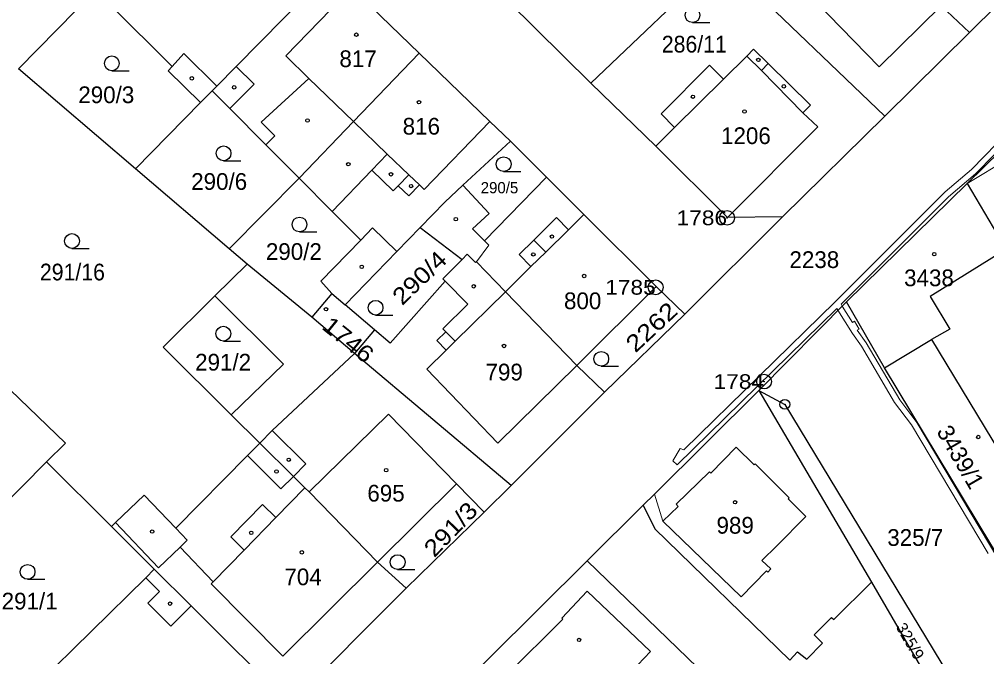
# Model space of a CAD drawing. Extents: x -679733 to -673243, y -1075091 to -1066557.
# Drawn here: x -676172.4 to -676074.1, y -1072237.3 to -1072172.5 of the extents above; entities that cross this region are included whole.
import ezdxf
from ezdxf.enums import TextEntityAlignment as Align

# ---------------------------------------------------------------- set-up
doc = ezdxf.new("R2010")
doc.units = 0
doc.header["$LTSCALE"] = 0.68
for name, color, linetype, lineweight in [('1', 7, 'Continuous', 25), ('13', 7, 'Continuous', 13), ('3', 7, 'Continuous', 25), ('4', 7, 'Continuous', 13), ('5', 7, 'Continuous', 25), ('8', 7, 'Continuous', 25)]:
    doc.layers.add(name, color=color, linetype=linetype, lineweight=lineweight)
doc.layers.add('2', color=7, linetype='Continuous')

msp = doc.modelspace()

# ---------------------------------------------------------------- linework, layer by layer
at = {"layer": '1'}
for p, q in [((-676075.84, -1072173.87), (-676078.75, -1072171.15)), ((-676160.6, -1072187.71), (-676153.99, -1072180.99)), ((-676127.33, -1072189.39), (-676122.5, -1072184.89)), ((-676143.98, -1072188.65), (-676151.09, -1072195.83)), ((-676088.36, -1072201.21), (-676076.09, -1072189.19)), ((-676149.25, -1072197.4), (-676151.09, -1072195.83)), ((-676140.66, -1072200.39), (-676142.69, -1072202.8)), ((-676115.76, -1072207.69), (-676107.7, -1072199.66)), ((-676088.36, -1072201.21), (-676097.27, -1072210.23)), ((-676136.31, -1072204.07), (-676139.3, -1072201.54)), ((-676084.49, -1072207.92), (-676079.72, -1072205.04)), ((-676112.93, -1072210.41), (-676115.76, -1072207.69)), ((-676150.87, -1072212.69), (-676147.97, -1072215.57)), ((-676169.65, -1072217.48), (-676187.4, -1072235.45)), ((-676163.05, -1072224.05), (-676158.7, -1072228.38)), ((-676133.11, -1072230.32), (-676136.01, -1072227.69))]:
    msp.add_line(p, q, dxfattribs=at)
for points in [[(-676114.32, -1072179), (-676101.1, -1072166.37), (-676110.05, -1072157.72)], [(-676093.25, -1072157.15), (-676097.04, -1072160.75), (-676094.82, -1072163.1), (-676092.64, -1072161.04), (-676089.33, -1072164.53), (-676092.7, -1072167.81), (-676090.63, -1072169.93), (-676091.48, -1072170.75), (-676085.03, -1072177.36), (-676078.75, -1072171.15)], [(-676172.49, -1072177.56), (-676164.67, -1072169.55), (-676173.85, -1072160.2), (-676182.71, -1072169.41), (-676199.6, -1072184.73), (-676189.24, -1072194.84), (-676188.86, -1072195.21)], [(-676067.32, -1072165.41), (-676075.84, -1072173.87), (-676084.45, -1072182.35), (-676094.84, -1072192.6), (-676104.78, -1072202.48), (-676112.93, -1072210.41), (-676122.41, -1072219.9)], [(-676084.45, -1072182.35), (-676099.52, -1072167.9), (-676101.1, -1072166.37)], [(-676152.8, -1072179.78), (-676152.34, -1072179.32), (-676150.36, -1072177.31), (-676140.68, -1072167.47)], [(-676140.68, -1072167.47), (-676138.62, -1072169.32), (-676131.77, -1072175.96)], [(-676164.67, -1072169.55), (-676163.17, -1072171.05), (-676156.88, -1072177.31), (-676157.28, -1072177.76), (-676153.99, -1072180.99), (-676152.8, -1072179.78)], [(-676094.84, -1072192.6), (-676100.44, -1072192.66), (-676107.74, -1072185.42), (-676114.32, -1072179), (-676122.73, -1072170.71)], [(-676034.65, -1072192.81), (-676036.38, -1072190.81), (-676051.24, -1072176.19), (-676055.21, -1072180.26), (-676055.76, -1072179.69), (-676060.44, -1072174.77), (-676060.88, -1072174.31), (-676076.09, -1072189.19)], [(-676100.44, -1072192.66), (-676091.26, -1072183.44), (-676092.79, -1072182.02), (-676092.02, -1072181.24), (-676096.3, -1072177.02), (-676097.79, -1072175.55), (-676098.49, -1072176.26), (-676100.85, -1072178.6), (-676102.26, -1072177.17), (-676107.19, -1072182.14), (-676105.82, -1072183.52), (-676107.74, -1072185.42)], [(-676131.77, -1072175.96), (-676138.45, -1072182.9), (-676143.98, -1072188.65)], [(-676131.77, -1072175.96), (-676124.58, -1072182.9), (-676122.5, -1072184.89), (-676118.83, -1072188.57)], [(-676151.09, -1072195.83), (-676160.6, -1072187.71), (-676172.49, -1072177.56)], [(-676152.8, -1072179.78), (-676151, -1072181.59), (-676147.35, -1072185.26), (-676143.98, -1072188.65)], [(-676118.83, -1072188.57), (-676125.13, -1072195.02), (-676126.35, -1072193.81), (-676124.67, -1072192.24), (-676127.33, -1072189.39)], [(-676118.83, -1072188.57), (-676115.04, -1072192.36), (-676107.7, -1072199.66), (-676104.78, -1072202.48)], [(-676143.98, -1072188.65), (-676140.61, -1072192.04), (-676137.71, -1072194.95), (-676141.78, -1072199.14), (-676140.66, -1072200.39), (-676139.3, -1072201.54)], [(-676127.33, -1072189.39), (-676129.18, -1072191.11), (-676131.67, -1072193.67), (-676127.41, -1072196.92)], [(-676076.09, -1072189.19), (-676072.14, -1072195.9), (-676072.34, -1072196.02), (-676079.86, -1072200.68), (-676077.85, -1072203.99), (-676079.72, -1072205.04), (-676068.92, -1072222.89)], [(-676139.3, -1072201.54), (-676134.04, -1072196.12), (-676131.67, -1072193.67)], [(-676115.76, -1072207.69), (-676123, -1072200.2), (-676125.95, -1072197.15), (-676126.05, -1072197.24), (-676126.89, -1072196.4), (-676127.41, -1072196.92)], [(-676136.01, -1072227.69), (-676127.97, -1072219.71), (-676125.16, -1072222.58), (-676122.41, -1072219.9), (-676138.34, -1072206.48), (-676142.69, -1072202.8), (-676149.25, -1072197.4), (-676152.53, -1072200.63)], [(-676127.41, -1072196.92), (-676129.38, -1072198.88), (-676129.14, -1072199.12), (-676134.72, -1072205.41), (-676136.31, -1072204.07), (-676138.34, -1072206.48)], [(-676186.48, -1072197.53), (-676167.7, -1072215.6), (-676169.65, -1072217.48), (-676163.05, -1072224.05)], [(-676152.53, -1072200.63), (-676157.8, -1072205.82), (-676150.87, -1072212.69)], [(-676152.53, -1072200.63), (-676145.55, -1072207.57), (-676150.87, -1072212.69)], [(-676068.07, -1072234.95), (-676073.68, -1072225.83), (-676084.49, -1072207.92), (-676088.36, -1072201.21)], [(-676109, -1072221.89), (-676107.87, -1072220.76), (-676097.27, -1072210.23)], [(-676097.27, -1072210.23), (-676085.8, -1072229.69), (-676079, -1072241.43)], [(-676097.27, -1072210.23), (-676094.62, -1072211.64), (-676077.2, -1072240.39)], [(-676163.05, -1072224.05), (-676162.64, -1072223.66), (-676159.73, -1072220.87), (-676156.51, -1072224.23), (-676149.23, -1072216.85), (-676147.97, -1072215.57)], [(-676147.97, -1072215.57), (-676144.56, -1072218.96), (-676143.39, -1072220.12), (-676142.96, -1072220.54), (-676136.01, -1072227.69)], [(-676156.97, -1072269.5), (-676153.23, -1072265.81), (-676145.66, -1072258.33), (-676138.21, -1072250.89), (-676134.35, -1072247.07), (-676132.09, -1072244.81), (-676124.63, -1072237.4), (-676114.69, -1072227.54), (-676109, -1072221.89)], [(-676109, -1072221.89), (-676107.83, -1072224.3), (-676094.12, -1072237.62), (-676093.32, -1072236.79), (-676092.4, -1072237.54), (-676090.79, -1072235.9), (-676091.63, -1072235.07), (-676089.88, -1072233.29), (-676089.65, -1072233.51), (-676085.8, -1072229.69)], [(-676125.16, -1072222.58), (-676133.11, -1072230.32), (-676144.89, -1072242.13), (-676152.01, -1072249.22), (-676162.67, -1072259.88)], [(-676107.06, -1072243.57), (-676102.49, -1072239.34), (-676114.69, -1072227.54)], [(-676158.7, -1072228.38), (-676159.56, -1072229.25), (-676170.59, -1072240.11), (-676174.56, -1072244.03), (-676171.89, -1072246.75), (-676163.53, -1072255.26)], [(-676158.7, -1072228.38), (-676154.95, -1072232.11), (-676144.89, -1072242.13)]]:
    msp.add_lwpolyline(points, dxfattribs=at)
at = {"layer": '13'}
for points in [[(-676071.81, -1072183.85), (-676075.65, -1072187.79), (-676078.32, -1072190.04), (-676089.51, -1072201.22), (-676104.88, -1072216.27), (-676105.24, -1072216.14), (-676106.01, -1072217.38), (-676105.57, -1072217.79), (-676089.34, -1072201.89), (-676089.22, -1072202.08), (-676087.76, -1072204.45), (-676086.84, -1072205.74), (-676083.47, -1072211.47), (-676081.75, -1072213.73), (-676073.97, -1072226.78)], [(-676072.96, -1072227.31), (-676081.19, -1072213.49), (-676082.93, -1072211.19), (-676086.34, -1072205.4), (-676087.27, -1072204.1), (-676087.08, -1072203.99), (-676087.54, -1072203.2), (-676087.73, -1072203.31), (-676088.79, -1072201.65), (-676088.91, -1072201.46), (-676078, -1072190.56), (-676075.25, -1072188.23), (-676071.4, -1072184.29)]]:
    msp.add_lwpolyline(points, dxfattribs=at)
at = {"layer": '3'}
for p, q in [((-676104.003, -1072172.85), (-676102.253, -1072172.85)), ((-676163.003, -1072177.75), (-676161.253, -1072177.75)), ((-676151.653, -1072186.89), (-676149.903, -1072186.89)), ((-676123.193, -1072187.99), (-676121.443, -1072187.99)), ((-676143.933, -1072194.12), (-676142.183, -1072194.12)), ((-676167.053, -1072195.8), (-676165.303, -1072195.8)), ((-676136.203, -1072202.58), (-676134.453, -1072202.58)), ((-676151.673, -1072205.21), (-676149.923, -1072205.21)), ((-676113.273, -1072207.77), (-676111.523, -1072207.77)), ((-676133.963, -1072228.42), (-676132.213, -1072228.42)), ((-676171.563, -1072229.41), (-676169.813, -1072229.41))]:
    msp.add_line(p, q, dxfattribs=at)
for centre in [(-676104.0029, -1072172.0998), (-676163.0029, -1072176.9998), (-676151.6529, -1072186.1398), (-676123.1929, -1072187.2398), (-676143.9329, -1072193.3698), (-676167.0529, -1072195.0498), (-676136.2029, -1072201.8298), (-676151.6729, -1072204.4598), (-676113.2729, -1072207.0198), (-676133.9629, -1072227.6698), (-676171.5629, -1072228.6598)]:
    msp.add_circle(centre, 0.75, dxfattribs=at)
at = {"layer": '4'}
for p, q in [((-676145.34, -1072176.25), (-676138.62, -1072169.32)), ((-676156.88, -1072177.31), (-676155.7, -1072176.01)), ((-676155.7, -1072176.01), (-676152.34, -1072179.32)), ((-676142.98, -1072178.53), (-676145.34, -1072176.25)), ((-676098.49, -1072176.26), (-676097, -1072177.73)), ((-676150.36, -1072177.31), (-676148.54, -1072179.1)), ((-676097, -1072177.73), (-676096.3, -1072177.02)), ((-676092.79, -1072182.02), (-676097, -1072177.73)), ((-676147.82, -1072182.98), (-676142.98, -1072178.53)), ((-676142.98, -1072178.53), (-676138.45, -1072182.9)), ((-676105.82, -1072183.52), (-676100.85, -1072178.6)), ((-676148.54, -1072179.1), (-676151, -1072181.59)), ((-676146.45, -1072184.36), (-676147.82, -1072182.98)), ((-676135.01, -1072186.21), (-676138.45, -1072182.9)), ((-676131.26, -1072189.82), (-676124.58, -1072182.9)), ((-676076.09, -1072189.19), (-676066.75, -1072183.55)), ((-676147.35, -1072185.26), (-676146.45, -1072184.36)), ((-676135.01, -1072186.21), (-676136.59, -1072187.86)), ((-676132.83, -1072188.31), (-676135.01, -1072186.21)), ((-676136.59, -1072187.86), (-676140.61, -1072192.04)), ((-676136.59, -1072187.86), (-676134.4, -1072189.96)), ((-676133.9, -1072189.43), (-676132.83, -1072188.31)), ((-676131.75, -1072189.35), (-676132.83, -1072188.31)), ((-676134.4, -1072189.96), (-676133.9, -1072189.43)), ((-676132.82, -1072190.46), (-676133.9, -1072189.43)), ((-676131.75, -1072189.35), (-676132.82, -1072190.46)), ((-676131.26, -1072189.82), (-676131.75, -1072189.35)), ((-676116.61, -1072193.9), (-676115.04, -1072192.36)), ((-676120.14, -1072194.95), (-676117.82, -1072192.66)), ((-676117.82, -1072192.66), (-676116.61, -1072193.9)), ((-676136.52, -1072193.72), (-676137.71, -1072194.95)), ((-676134.04, -1072196.12), (-676136.52, -1072193.72)), ((-676118.92, -1072196.18), (-676116.61, -1072193.9)), ((-676125.95, -1072197.15), (-676124.68, -1072195.46)), ((-676124.68, -1072195.46), (-676125.13, -1072195.02)), ((-676121.63, -1072196.42), (-676120.14, -1072194.95)), ((-676118.92, -1072196.18), (-676120.14, -1072194.95)), ((-676120.42, -1072197.65), (-676121.63, -1072196.42)), ((-676120.42, -1072197.65), (-676118.92, -1072196.18)), ((-676123, -1072200.2), (-676120.42, -1072197.65)), ((-676129.14, -1072199.12), (-676126.82, -1072201.45)), ((-676128.11, -1072205.23), (-676123, -1072200.2)), ((-676126.82, -1072201.45), (-676129.37, -1072203.96)), ((-676129.07, -1072204.26), (-676129.98, -1072205.16)), ((-676129.37, -1072203.96), (-676129.07, -1072204.26)), ((-676129.07, -1072204.26), (-676128.11, -1072205.23)), ((-676129.98, -1072205.16), (-676129.02, -1072206.13)), ((-676129.02, -1072206.13), (-676128.11, -1072205.23)), ((-676129.02, -1072206.13), (-676130.98, -1072208.06)), ((-676146.7, -1072214.3), (-676138.34, -1072206.48)), ((-676130.98, -1072208.06), (-676123.79, -1072215.59)), ((-676123.79, -1072215.59), (-676115.76, -1072207.69)), ((-676134.88, -1072212.64), (-676142.96, -1072220.54)), ((-676127.97, -1072219.71), (-676134.88, -1072212.64)), ((-676147.97, -1072215.57), (-676146.7, -1072214.3)), ((-676146.7, -1072214.3), (-676143.29, -1072217.68)), ((-676099.57, -1072216), (-676102.14, -1072218.64)), ((-676097.75, -1072217.8), (-676099.57, -1072216)), ((-676145.83, -1072220.23), (-676149.23, -1072216.85)), ((-676143.29, -1072217.68), (-676144.56, -1072218.96)), ((-676097.65, -1072217.7), (-676097.75, -1072217.8)), ((-676094.19, -1072221.13), (-676097.65, -1072217.7)), ((-676144.56, -1072218.96), (-676145.83, -1072220.23)), ((-676102.27, -1072218.51), (-676105.67, -1072221.78)), ((-676102.14, -1072218.64), (-676102.27, -1072218.51)), ((-676143.39, -1072220.12), (-676146.34, -1072223.15)), ((-676107.01, -1072223.51), (-676107.87, -1072220.76)), ((-676147.7, -1072221.82), (-676150.92, -1072225.11)), ((-676146.34, -1072223.15), (-676147.7, -1072221.82)), ((-676105.46, -1072222.02), (-676105.67, -1072221.78)), ((-676094.29, -1072221.23), (-676094.19, -1072221.13)), ((-676092.49, -1072223.02), (-676094.29, -1072221.23)), ((-676107.01, -1072223.51), (-676105.46, -1072222.02)), ((-676158.25, -1072228.24), (-676162.64, -1072223.66)), ((-676149.56, -1072226.44), (-676146.34, -1072223.15)), ((-676107.01, -1072223.51), (-676099.07, -1072231.21)), ((-676095.44, -1072226), (-676092.49, -1072223.02)), ((-676155.34, -1072225.45), (-676156.51, -1072224.23)), ((-676156.07, -1072226.15), (-676155.34, -1072225.45)), ((-676150.92, -1072225.11), (-676149.56, -1072226.44)), ((-676156.07, -1072226.15), (-676158.25, -1072228.24)), ((-676152.7, -1072229.66), (-676156.07, -1072226.15)), ((-676149.56, -1072226.44), (-676152.7, -1072229.66)), ((-676096.94, -1072227.51), (-676095.44, -1072226)), ((-676136.01, -1072227.69), (-676145.62, -1072237.22)), ((-676096.03, -1072228.35), (-676096.94, -1072227.51)), ((-676099.07, -1072231.21), (-676096.49, -1072228.54)), ((-676096.49, -1072228.54), (-676096.35, -1072228.68)), ((-676096.35, -1072228.68), (-676096.03, -1072228.35)), ((-676159.56, -1072229.25), (-676158.16, -1072230.64)), ((-676152.91, -1072229.87), (-676152.7, -1072229.66)), ((-676145.62, -1072237.22), (-676152.91, -1072229.87)), ((-676158.16, -1072230.64), (-676159.36, -1072231.85)), ((-676117.27, -1072233.37), (-676114.71, -1072230.63)), ((-676114.71, -1072230.63), (-676108.28, -1072236.74)), ((-676159.36, -1072231.85), (-676157.01, -1072234.18)), ((-676157.01, -1072234.18), (-676154.95, -1072232.11)), ((-676122.89, -1072239.16), (-676117.16, -1072233.48)), ((-676117.16, -1072233.48), (-676117.27, -1072233.37)), ((-676108.28, -1072236.74), (-676115.38, -1072244.22))]:
    msp.add_line(p, q, dxfattribs=at)
at = {"layer": '5'}
for centre in [(-676138.1568, -1072174.0892), (-676097.3068, -1072176.6492), (-676154.8768, -1072178.5192), (-676150.5768, -1072179.4392), (-676094.7168, -1072179.3392), (-676103.9568, -1072180.3892), (-676131.7968, -1072180.9492), (-676098.7168, -1072181.8892), (-676143.1268, -1072182.8092), (-676138.9768, -1072187.2492), (-676134.6368, -1072188.2692), (-676132.5968, -1072189.4692), (-676128.0468, -1072192.8292), (-676118.2868, -1072194.5992), (-676120.1768, -1072196.4092), (-676079.4368, -1072196.3792), (-676137.6068, -1072197.6692), (-676115.0068, -1072198.5992), (-676126.2268, -1072199.6492), (-676141.2368, -1072201.9792), (-676123.1568, -1072205.7092), (-676074.9668, -1072214.9592), (-676145.0268, -1072217.2692), (-676146.2668, -1072218.4592), (-676135.1268, -1072218.3292), (-676099.6768, -1072221.5892), (-676158.9068, -1072224.5692), (-676148.8368, -1072224.6892), (-676143.6968, -1072226.6692), (-676157.0868, -1072231.8892), (-676115.5268, -1072235.5692)]:
    msp.add_circle(centre, 0.175, dxfattribs=at)
at = {"layer": '8'}
for centre, radius in [((-676100.49, -1072192.6898), 0.75), ((-676100.49, -1072192.6898), 0.03), ((-676107.74, -1072199.7498), 0.75), ((-676107.74, -1072199.7498), 0.03), ((-676096.73, -1072209.3298), 0.75), ((-676096.73, -1072209.3298), 0.03), ((-676094.62, -1072211.6399), 0.5), ((-676094.62, -1072211.6399), 0.0303)]:
    msp.add_circle(centre, radius, dxfattribs=at)

# ---------------------------------------------------------------- texts
at = {"layer": '2', "width": 0.95}
for s, p in [('286/11', (-676107.12, -1072175.9)), ('291/16', (-676170.31, -1072199.05))]:
    msp.add_text(s, height=1.7, dxfattribs=at).set_placement(p)
at = {"layer": '2'}
for s, height, p in [('817', 1.7, (-676139.88, -1072177.38)), ('290/3', 1.7, (-676166.41, -1072181.04)), ('816', 1.7, (-676133.45, -1072184.239)), ('1206', 1.7, (-676101.1, -1072185.2)), ('290/6', 1.7, (-676154.94, -1072189.85)), ('290/5', 1.14, (-676125.52, -1072190.199)), ('290/2', 1.7, (-676147.35, -1072196.97)), ('2238', 1.7, (-676094.15, -1072197.79)), ('3438', 1.7, (-676082.5, -1072199.64)), ('800', 1.7, (-676117.06, -1072201.97)), ('291/2', 1.7, (-676154.54, -1072208.21)), ('799', 1.7, (-676125.03, -1072209.21)), ('695', 1.7, (-676137.04, -1072221.519)), ('989', 1.7, (-676101.56, -1072224.779)), ('325/7', 1.7, (-676084.21, -1072226.019)), ('704', 1.7, (-676145.47, -1072230.019)), ('291/1', 1.7, (-676174.2, -1072232.479))]:
    msp.add_text(s, height=height, dxfattribs=at).set_placement(p)
for s, height, rotation, width, p in [('290/4', 1.7, 44, 1.15, (-676133.499, -1072201.661)), ('2262', 1.7, 43, 1.2, (-676109.81, -1072206.481)), ('1746', 1.7, 321, 1.15, (-676141.774, -1072203.9)), ('291/3', 1.7, 46, 1.15, (-676130.238, -1072227.27)), ('325/9', 1.14, 300, 1.05, (-676083.383, -1072234.245))]:
    msp.add_text(s, height=height, rotation=rotation, dxfattribs=dict(at, width=width)).set_placement(p)
msp.add_text('3439/1', height=1.7, rotation=300, dxfattribs=at).set_placement((-676079.246, -1072214.395))
at = {"layer": '8', "width": 1.15}
for s, p in [('1786', (-676100.489, -1072193.44)), ('1785', (-676107.739, -1072200.5)), ('1784', (-676096.729, -1072210.08))]:
    msp.add_text(s, height=1.5, dxfattribs=at).set_placement(p, align=Align.RIGHT)

doc.saveas('drawing.dxf')
